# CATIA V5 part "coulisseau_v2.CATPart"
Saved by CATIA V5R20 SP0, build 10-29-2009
Part number: coulisseau_v2
Bounding box of the stored display mesh (mm): x -10 to 20, y 35.789 to 65.904, z -21.34 to 28.66
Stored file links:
  D:\thinkmotion-MPB\Dropbox\IAO_2011\MMS_GR3\aweinling\aweinling\coulisseau_v2.CATPart
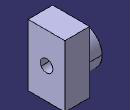
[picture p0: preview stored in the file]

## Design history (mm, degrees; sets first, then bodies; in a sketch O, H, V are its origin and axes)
Parameters
  D_Trou = 10 mm
  D_Pivot = 30 mm
Body1 (main body)
  Sketch1 on yz-plane, origin (0, 0, 0), H (0, 1, 0), V (0, 0, 1)
    line L1 (35.7886, 28.6597) -> (65.7886, 28.6597)
    line L2 (65.7886, 28.6597) -> (65.7886, -21.3403)
    line L3 (65.7886, -21.3403) -> (35.7886, -21.3403)
    line L4 (35.7886, -21.3403) -> (35.7886, 28.6597)
    length L3 = 30
    length L2 = 50
    horizontal: L1 H, L3 H
    vertical: L2 V, L4 V
  Pad1: profile Sketch1, direction (1, 0, 0), length 20
  Sketch2 on yz-plane, origin (0, 0, 0), H (0, 1, 0), V (0, 0, 1)
    circle A1 centre (50.9042, 3.6597) radius 15
    point P1 (50.9042, 3.6597)
    reference projected line E1 (65.7886, 28.6597) -> (35.7886, 28.6597) from edge [face of Pad1 from Sketch1.L1 | end face of Pad1]
    radius A1 = 15 {= D_Pivot /2}
    distance P1 E1 = 25
  Pad2: profile Sketch2, direction (-1, 0, 0), length 10
  Sketch3 on end face of Pad2, origin (-10, 50.9042, 3.6597), H (0, 1, 0), V (0, 0, -1)
    point P1 (0, 0)
    reference projected circle E1 centre (0, 0) radius 15 from edge [end face of Pad2 | face of Pad2 from Sketch2.A1]
    concentricity: P1 E1
  Hole1: placed by Sketch3, at (-10, 50.9042, 3.6597) direction (1, 0, 0), diameter 10 {= D_Trou}, through (limit type 3)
